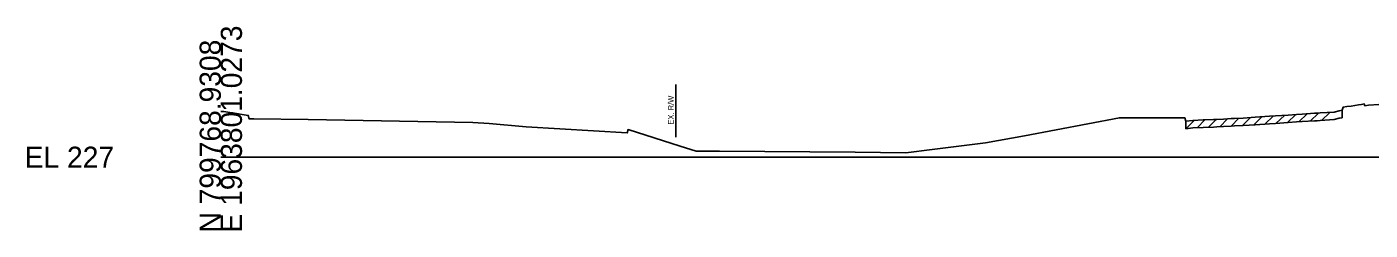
# Model space of a CAD drawing. Extents: x -26 to 1403, y -10 to 19587.
# Drawn here: x -25.7 to 152.2, y 18490.3 to 18517.3 of the extents above; entities that cross this region are included whole.
import ezdxf

# ---------------------------------------------------------------- set-up
doc = ezdxf.new("R2010")
doc.units = 0
for name, color, linetype in [('Default', 7, 'Continuous'), ('RD_GPK_XS_Cell', 7, 'Continuous'), ('RD_XS_ExGround', 7, 'Continuous'), ('RD_XS_ExPaveRet', 7, 'Continuous'), ('RD_XS_ExRW', 7, 'Continuous')]:
    doc.layers.add(name, color=color, linetype=linetype)

msp = doc.modelspace()

# ---------------------------------------------------------------- linework, layer by layer
at = {"layer": 'RD_GPK_XS_Cell'}
msp.add_line((0, 18500), (200, 18500), dxfattribs=at)
at = {"layer": 'RD_XS_ExGround'}
msp.add_lwpolyline([(0, 18506.07), (0.4, 18506.05), (1.2, 18505.96), (1.55, 18505.91), (3.63, 18505.55), (3.74, 18505.1), (4.38, 18505.11), (11.56, 18504.99), (33.39, 18504.61), (35.55, 18504.48), (40.45, 18504.05), (53.85, 18503.23), (53.96, 18503.68), (60.86, 18501.47), (62.95, 18500.82), (66.05, 18500.81), (84.02, 18500.69), (90.73, 18500.59), (94.22, 18501.01), (101.29, 18501.93), (106.46, 18502.86), (119.04, 18505.24), (120.58, 18505.23), (127.71, 18505.22), (127.82, 18504.77), (128.76, 18504.89), (130.14, 18504.96), (131.51, 18505.01), (131.93, 18505.03), (132.84, 18505.07), (133.85, 18505.12), (134.29, 18505.15), (135.45, 18505.2), (137.01, 18505.3), (138.91, 18505.44), (139.71, 18505.49), (141.41, 18505.6), (142.51, 18505.69), (143.26, 18505.73), (144.9, 18505.84), (145.21, 18505.85), (145.62, 18505.88), (147.48, 18506), (148.15, 18506.17), (148.55, 18506.23), (148.66, 18506.63), (149.15, 18506.72), (149.72, 18506.8), (150.71, 18506.96), (151.11, 18507.02), (151.45, 18507.08), (151.56, 18506.83), (152.03, 18506.89), (156.12, 18507.17)], dxfattribs=at)
at = {"layer": 'RD_XS_ExPaveRet'}
for p, q in [((144.32, 18504.8), (145.39, 18505.87)), ((145.82, 18504.89), (146.89, 18505.96)), ((148.55, 18506.23), (148.55, 18505.23)), ((127.82, 18503.77), (128.96, 18504.9)), ((127.82, 18503.77), (127.82, 18504.77)), ((129.32, 18503.92), (130.37, 18504.96)), ((130.82, 18503.98), (131.87, 18505.03)), ((132.32, 18504.05), (133.37, 18505.1)), ((132.84, 18504.07), (133.85, 18504.12)), ((133.82, 18504.12), (134.87, 18505.18)), ((133.85, 18504.12), (134.29, 18504.15)), ((134.29, 18504.15), (135.45, 18504.2)), ((135.32, 18504.2), (136.38, 18505.26)), ((135.45, 18504.2), (137.01, 18504.3)), ((136.82, 18504.29), (137.9, 18505.36)), ((137.01, 18504.3), (138.91, 18504.44)), ((138.32, 18504.39), (139.4, 18505.47)), ((138.91, 18504.44), (139.71, 18504.49)), ((139.71, 18504.49), (141.41, 18504.6)), ((139.82, 18504.5), (140.89, 18505.56)), ((141.32, 18504.59), (142.41, 18505.68)), ((141.41, 18504.6), (142.51, 18504.69)), ((142.51, 18504.69), (143.26, 18504.73)), ((142.82, 18504.71), (143.89, 18505.77)), ((143.26, 18504.73), (144.9, 18504.84)), ((144.9, 18504.84), (145.21, 18504.85)), ((145.21, 18504.85), (145.62, 18504.88)), ((145.62, 18504.88), (147.48, 18505)), ((147.48, 18505), (148.15, 18505.17)), ((148.15, 18505.17), (148.55, 18505.23)), ((148.55, 18505.23), (148.55, 18505.23)), ((127.82, 18503.77), (128.76, 18503.89)), ((128.76, 18503.89), (130.14, 18503.96)), ((130.14, 18503.96), (131.51, 18504.01)), ((131.51, 18504.01), (131.93, 18504.03)), ((131.93, 18504.03), (132.84, 18504.07))]:
    msp.add_line(p, q, dxfattribs=at)
at = {"layer": 'RD_XS_ExRW'}
msp.add_line((60.29, 18502.66), (60.29, 18509.66), dxfattribs=at)

# ---------------------------------------------------------------- texts
at = {"layer": 'Default'}
msp.add_text('-', height=0.0001, dxfattribs=at).set_placement((0, 18500))
at = {"layer": 'RD_GPK_XS_Cell'}
for s, p in [('E 1963801.0273', (2.8, 18490)), ('N 799768.9308', (0, 18490))]:
    msp.add_text(s, height=2.8, rotation=90, dxfattribs=at).set_placement(p)
msp.add_text('EL 227', height=2.8, dxfattribs=at).set_placement((-26, 18498.6))
at = {"layer": 'RD_XS_ExRW'}
msp.add_text('EX. R/W ', height=0.75, rotation=90, dxfattribs=at).set_placement((60, 18504.33))

doc.saveas('drawing.dxf')
